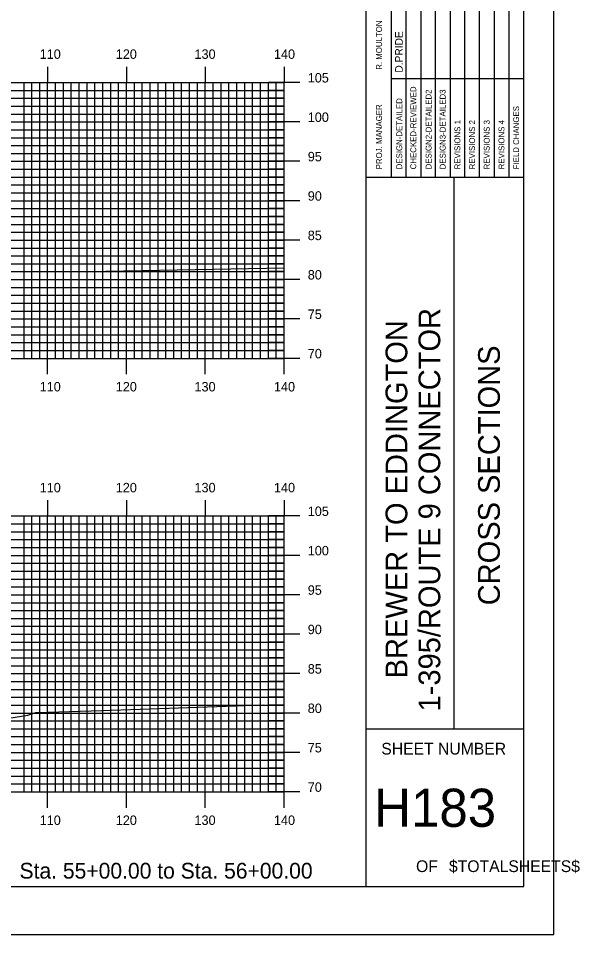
# Model space of a CAD drawing. Extents: x 1756675 to 1757019, y 442591 to 442811.
# Drawn here: x 1756947.4 to 1757018.6, y 442590.5 to 442706.8 of the extents above; entities that cross this region are included whole.
import ezdxf

# ---------------------------------------------------------------- set-up
doc = ezdxf.new("R2010")
doc.units = 0
for name, color, linetype in [('BORDER', 7, 'Continuous'), ('H_V ANNOTATION', 7, 'Continuous'), ('MAJOR', 7, 'Continuous'), ('MINOR', 7, 'Continuous'), ('PLOT BOUNDARY', 7, 'Continuous'), ('S_Roadway_Centerline', 7, 'Continuous')]:
    doc.layers.add(name, color=color, linetype=linetype)

msp = doc.modelspace()

# ---------------------------------------------------------------- linework, layer by layer
at = {"layer": 'BORDER'}
for p, q in [((1756991.48, 442596.67), (1756991.48, 442806.67)), ((1756991.48, 442686.67), (1757011.48, 442686.67)), ((1757002.66, 442616.67), (1757002.66, 442686.67)), ((1756991.48, 442616.67), (1757011.48, 442616.67))]:
    msp.add_line(p, q, dxfattribs=at)
msp.add_lwpolyline([(1756691.48, 442596.67), (1757011.48, 442596.67), (1757011.48, 442806.67), (1756691.48, 442806.67)], close=True, dxfattribs=at)
for points in [[(1756996.58, 442686.68), (1756996.58, 442721.67)], [(1756998.44, 442721.67), (1756998.44, 442686.68)], [(1757000.3, 442686.68), (1757000.3, 442721.67)], [(1757002.17, 442686.68), (1757002.17, 442721.67)], [(1757004.03, 442686.68), (1757004.03, 442721.67)], [(1757005.89, 442686.68), (1757005.89, 442721.67)], [(1757007.76, 442686.68), (1757007.76, 442721.67)], [(1757009.62, 442686.68), (1757009.62, 442721.67)], [(1756994.71, 442686.68), (1756994.71, 442720.26)], [(1756994.71, 442699.17), (1757011.48, 442699.17)]]:
    msp.add_lwpolyline(points, dxfattribs=at)
at = {"layer": 'MAJOR'}
for p, q in [((1756951.08, 442700.67), (1756951.08, 442698.67)), ((1756961.08, 442700.67), (1756961.08, 442698.67)), ((1756971.08, 442700.67), (1756971.08, 442698.67)), ((1756981.08, 442700.67), (1756981.08, 442698.67)), ((1756701.08, 442698.67), (1756981.08, 442698.67)), ((1756701.08, 442698.67), (1756981.08, 442698.67)), ((1756951.08, 442663.67), (1756951.08, 442698.67)), ((1756961.08, 442663.67), (1756961.08, 442698.67)), ((1756971.08, 442663.67), (1756971.08, 442698.67)), ((1756983.09, 442698.67), (1756979.08, 442698.67)), ((1756981.08, 442663.67), (1756981.08, 442698.67)), ((1756981.08, 442663.67), (1756981.08, 442698.67)), ((1756701.08, 442693.67), (1756981.08, 442693.67)), ((1756983.09, 442693.67), (1756979.08, 442693.67)), ((1756701.08, 442688.67), (1756981.08, 442688.67)), ((1756983.09, 442688.67), (1756979.08, 442688.67)), ((1756701.08, 442683.67), (1756981.08, 442683.67)), ((1756983.09, 442683.67), (1756979.08, 442683.67)), ((1756701.08, 442678.67), (1756981.08, 442678.67)), ((1756983.09, 442678.67), (1756979.08, 442678.67)), ((1756701.08, 442673.67), (1756981.08, 442673.67)), ((1756983.09, 442673.67), (1756979.08, 442673.67)), ((1756701.08, 442668.67), (1756981.08, 442668.67)), ((1756983.09, 442668.67), (1756979.08, 442668.67)), ((1756701.08, 442663.67), (1756981.08, 442663.67)), ((1756701.08, 442663.67), (1756981.08, 442663.67)), ((1756951.08, 442661.66), (1756951.08, 442663.67)), ((1756961.08, 442661.66), (1756961.08, 442663.67)), ((1756971.08, 442661.66), (1756971.08, 442663.67)), ((1756983.09, 442663.67), (1756979.08, 442663.67)), ((1756981.08, 442661.66), (1756981.08, 442663.67)), ((1756951.08, 442645.67), (1756951.08, 442643.67)), ((1756961.08, 442645.67), (1756961.08, 442643.67)), ((1756971.08, 442645.67), (1756971.08, 442643.67)), ((1756981.08, 442645.67), (1756981.08, 442643.67)), ((1756701.08, 442643.67), (1756981.08, 442643.67)), ((1756701.08, 442643.67), (1756981.08, 442643.67)), ((1756951.08, 442608.67), (1756951.08, 442643.67)), ((1756961.08, 442608.67), (1756961.08, 442643.67)), ((1756971.08, 442608.67), (1756971.08, 442643.67)), ((1756983.09, 442643.67), (1756979.08, 442643.67)), ((1756981.08, 442608.67), (1756981.08, 442643.67)), ((1756981.08, 442608.67), (1756981.08, 442643.67)), ((1756701.08, 442638.67), (1756981.08, 442638.67)), ((1756983.09, 442638.67), (1756979.08, 442638.67)), ((1756701.08, 442633.67), (1756981.08, 442633.67)), ((1756983.09, 442633.67), (1756979.08, 442633.67)), ((1756701.08, 442628.67), (1756981.08, 442628.67)), ((1756983.09, 442628.67), (1756979.08, 442628.67)), ((1756701.08, 442623.67), (1756981.08, 442623.67)), ((1756983.09, 442623.67), (1756979.08, 442623.67)), ((1756701.08, 442618.67), (1756981.08, 442618.67)), ((1756983.09, 442618.67), (1756979.08, 442618.67)), ((1756701.08, 442613.67), (1756981.08, 442613.67)), ((1756983.09, 442613.67), (1756979.08, 442613.67)), ((1756701.08, 442608.67), (1756981.08, 442608.67)), ((1756701.08, 442608.67), (1756981.08, 442608.67)), ((1756951.08, 442606.66), (1756951.08, 442608.67)), ((1756961.08, 442606.66), (1756961.08, 442608.67)), ((1756971.08, 442606.66), (1756971.08, 442608.67)), ((1756983.09, 442608.67), (1756979.08, 442608.67)), ((1756981.08, 442606.66), (1756981.08, 442608.67))]:
    msp.add_line(p, q, dxfattribs=at)
at = {"layer": 'MINOR'}
for p, q in [((1756948.08, 442663.67), (1756948.08, 442698.67)), ((1756949.08, 442663.67), (1756949.08, 442698.67)), ((1756950.08, 442663.67), (1756950.08, 442698.67)), ((1756952.08, 442663.67), (1756952.08, 442698.67)), ((1756953.08, 442663.67), (1756953.08, 442698.67)), ((1756954.08, 442663.67), (1756954.08, 442698.67)), ((1756955.08, 442663.67), (1756955.08, 442698.67)), ((1756956.08, 442663.67), (1756956.08, 442698.67)), ((1756957.08, 442663.67), (1756957.08, 442698.67)), ((1756958.08, 442663.67), (1756958.08, 442698.67)), ((1756959.08, 442663.67), (1756959.08, 442698.67)), ((1756960.08, 442663.67), (1756960.08, 442698.67)), ((1756962.08, 442663.67), (1756962.08, 442698.67)), ((1756963.08, 442663.67), (1756963.08, 442698.67)), ((1756964.08, 442663.67), (1756964.08, 442698.67)), ((1756965.08, 442663.67), (1756965.08, 442698.67)), ((1756966.08, 442663.67), (1756966.08, 442698.67)), ((1756967.08, 442663.67), (1756967.08, 442698.67)), ((1756968.08, 442663.67), (1756968.08, 442698.67)), ((1756969.08, 442663.67), (1756969.08, 442698.67)), ((1756970.08, 442663.67), (1756970.08, 442698.67)), ((1756972.08, 442663.67), (1756972.08, 442698.67)), ((1756973.08, 442663.67), (1756973.08, 442698.67)), ((1756974.08, 442663.67), (1756974.08, 442698.67)), ((1756975.08, 442663.67), (1756975.08, 442698.67)), ((1756976.08, 442663.67), (1756976.08, 442698.67)), ((1756977.08, 442663.67), (1756977.08, 442698.67)), ((1756978.08, 442663.67), (1756978.08, 442698.67)), ((1756979.08, 442663.67), (1756979.08, 442698.67)), ((1756980.08, 442663.67), (1756980.08, 442698.67)), ((1756701.08, 442697.67), (1756981.08, 442697.67)), ((1756981.08, 442697.67), (1756979.08, 442697.67)), ((1756701.08, 442696.67), (1756981.08, 442696.67)), ((1756981.08, 442696.67), (1756979.08, 442696.67)), ((1756701.08, 442695.67), (1756981.08, 442695.67)), ((1756981.08, 442695.67), (1756979.08, 442695.67)), ((1756701.08, 442694.67), (1756981.08, 442694.67)), ((1756981.08, 442694.67), (1756979.08, 442694.67)), ((1756701.08, 442692.67), (1756981.08, 442692.67)), ((1756701.08, 442691.67), (1756981.08, 442691.67)), ((1756981.08, 442692.67), (1756979.08, 442692.67)), ((1756981.08, 442691.67), (1756979.08, 442691.67)), ((1756701.08, 442690.67), (1756981.08, 442690.67)), ((1756981.08, 442690.67), (1756979.08, 442690.67)), ((1756701.08, 442689.67), (1756981.08, 442689.67)), ((1756981.08, 442689.67), (1756979.08, 442689.67)), ((1756701.08, 442687.67), (1756981.08, 442687.67)), ((1756981.08, 442687.67), (1756979.08, 442687.67)), ((1756701.08, 442686.67), (1756981.08, 442686.67)), ((1756981.08, 442686.67), (1756979.08, 442686.67)), ((1756701.08, 442685.67), (1756981.08, 442685.67)), ((1756701.08, 442684.67), (1756981.08, 442684.67)), ((1756981.08, 442685.67), (1756979.08, 442685.67)), ((1756981.08, 442684.67), (1756979.08, 442684.67)), ((1756701.08, 442682.67), (1756981.08, 442682.67)), ((1756981.08, 442682.67), (1756979.08, 442682.67)), ((1756701.08, 442681.67), (1756981.08, 442681.67)), ((1756981.08, 442681.67), (1756979.08, 442681.67)), ((1756701.08, 442680.67), (1756981.08, 442680.67)), ((1756981.08, 442680.67), (1756979.08, 442680.67)), ((1756701.08, 442679.67), (1756981.08, 442679.67)), ((1756981.08, 442679.67), (1756979.08, 442679.67)), ((1756701.08, 442677.67), (1756981.08, 442677.67)), ((1756701.08, 442676.67), (1756981.08, 442676.67)), ((1756981.08, 442677.67), (1756979.08, 442677.67)), ((1756981.08, 442676.67), (1756979.08, 442676.67)), ((1756701.08, 442675.67), (1756981.08, 442675.67)), ((1756981.08, 442675.67), (1756979.08, 442675.67)), ((1756701.08, 442674.67), (1756981.08, 442674.67)), ((1756981.08, 442674.67), (1756979.08, 442674.67)), ((1756701.08, 442672.67), (1756981.08, 442672.67)), ((1756981.08, 442672.67), (1756979.08, 442672.67)), ((1756701.08, 442671.67), (1756981.08, 442671.67)), ((1756981.08, 442671.67), (1756979.08, 442671.67)), ((1756701.08, 442670.67), (1756981.08, 442670.67)), ((1756701.08, 442669.67), (1756981.08, 442669.67)), ((1756981.08, 442670.67), (1756979.08, 442670.67)), ((1756981.08, 442669.67), (1756979.08, 442669.67)), ((1756701.08, 442667.67), (1756981.08, 442667.67)), ((1756981.08, 442667.67), (1756979.08, 442667.67)), ((1756701.08, 442666.67), (1756981.08, 442666.67)), ((1756981.08, 442666.67), (1756979.08, 442666.67)), ((1756701.08, 442665.67), (1756981.08, 442665.67)), ((1756981.08, 442665.67), (1756979.08, 442665.67)), ((1756701.08, 442664.67), (1756981.08, 442664.67)), ((1756981.08, 442664.67), (1756979.08, 442664.67)), ((1756948.08, 442608.67), (1756948.08, 442643.67)), ((1756949.08, 442608.67), (1756949.08, 442643.67)), ((1756950.08, 442608.67), (1756950.08, 442643.67)), ((1756952.08, 442608.67), (1756952.08, 442643.67)), ((1756953.08, 442608.67), (1756953.08, 442643.67)), ((1756954.08, 442608.67), (1756954.08, 442643.67)), ((1756955.08, 442608.67), (1756955.08, 442643.67)), ((1756956.08, 442608.67), (1756956.08, 442643.67)), ((1756957.08, 442608.67), (1756957.08, 442643.67)), ((1756958.08, 442608.67), (1756958.08, 442643.67)), ((1756959.08, 442608.67), (1756959.08, 442643.67)), ((1756960.08, 442608.67), (1756960.08, 442643.67)), ((1756962.08, 442608.67), (1756962.08, 442643.67)), ((1756963.08, 442608.67), (1756963.08, 442643.67)), ((1756964.08, 442608.67), (1756964.08, 442643.67)), ((1756965.08, 442608.67), (1756965.08, 442643.67)), ((1756966.08, 442608.67), (1756966.08, 442643.67)), ((1756967.08, 442608.67), (1756967.08, 442643.67)), ((1756968.08, 442608.67), (1756968.08, 442643.67)), ((1756969.08, 442608.67), (1756969.08, 442643.67)), ((1756970.08, 442608.67), (1756970.08, 442643.67)), ((1756972.08, 442608.67), (1756972.08, 442643.67)), ((1756973.08, 442608.67), (1756973.08, 442643.67)), ((1756974.08, 442608.67), (1756974.08, 442643.67)), ((1756975.08, 442608.67), (1756975.08, 442643.67)), ((1756976.08, 442608.67), (1756976.08, 442643.67)), ((1756977.08, 442608.67), (1756977.08, 442643.67)), ((1756978.08, 442608.67), (1756978.08, 442643.67)), ((1756979.08, 442608.67), (1756979.08, 442643.67)), ((1756980.08, 442608.67), (1756980.08, 442643.67)), ((1756701.08, 442642.67), (1756981.08, 442642.67)), ((1756701.08, 442641.67), (1756981.08, 442641.67)), ((1756981.08, 442642.67), (1756979.08, 442642.67)), ((1756981.08, 442641.67), (1756979.08, 442641.67)), ((1756701.08, 442640.67), (1756981.08, 442640.67)), ((1756981.08, 442640.67), (1756979.08, 442640.67)), ((1756701.08, 442639.67), (1756981.08, 442639.67)), ((1756981.08, 442639.67), (1756979.08, 442639.67)), ((1756701.08, 442637.67), (1756981.08, 442637.67)), ((1756981.08, 442637.67), (1756979.08, 442637.67)), ((1756701.08, 442636.67), (1756981.08, 442636.67)), ((1756981.08, 442636.67), (1756979.08, 442636.67)), ((1756701.08, 442635.67), (1756981.08, 442635.67)), ((1756701.08, 442634.67), (1756981.08, 442634.67)), ((1756981.08, 442635.67), (1756979.08, 442635.67)), ((1756981.08, 442634.67), (1756979.08, 442634.67)), ((1756701.08, 442632.67), (1756981.08, 442632.67)), ((1756981.08, 442632.67), (1756979.08, 442632.67)), ((1756701.08, 442631.67), (1756981.08, 442631.67)), ((1756981.08, 442631.67), (1756979.08, 442631.67)), ((1756701.08, 442630.67), (1756981.08, 442630.67)), ((1756981.08, 442630.67), (1756979.08, 442630.67)), ((1756701.08, 442629.67), (1756981.08, 442629.67)), ((1756981.08, 442629.67), (1756979.08, 442629.67)), ((1756701.08, 442627.67), (1756981.08, 442627.67)), ((1756701.08, 442626.67), (1756981.08, 442626.67)), ((1756981.08, 442627.67), (1756979.08, 442627.67)), ((1756981.08, 442626.67), (1756979.08, 442626.67)), ((1756701.08, 442625.67), (1756981.08, 442625.67)), ((1756981.08, 442625.67), (1756979.08, 442625.67)), ((1756701.08, 442624.67), (1756981.08, 442624.67)), ((1756981.08, 442624.67), (1756979.08, 442624.67)), ((1756701.08, 442622.67), (1756981.08, 442622.67)), ((1756981.08, 442622.67), (1756979.08, 442622.67)), ((1756701.08, 442621.67), (1756981.08, 442621.67)), ((1756981.08, 442621.67), (1756979.08, 442621.67)), ((1756701.08, 442620.67), (1756981.08, 442620.67)), ((1756701.08, 442619.67), (1756981.08, 442619.67)), ((1756981.08, 442620.67), (1756979.08, 442620.67)), ((1756981.08, 442619.67), (1756979.08, 442619.67)), ((1756701.08, 442617.67), (1756981.08, 442617.67)), ((1756981.08, 442617.67), (1756979.08, 442617.67)), ((1756701.08, 442616.67), (1756981.08, 442616.67)), ((1756981.08, 442616.67), (1756979.08, 442616.67)), ((1756701.08, 442615.67), (1756981.08, 442615.67)), ((1756981.08, 442615.67), (1756979.08, 442615.67)), ((1756701.08, 442614.67), (1756981.08, 442614.67)), ((1756981.08, 442614.67), (1756979.08, 442614.67)), ((1756701.08, 442612.67), (1756981.08, 442612.67)), ((1756981.08, 442612.67), (1756979.08, 442612.67)), ((1756701.08, 442611.67), (1756981.08, 442611.67)), ((1756981.08, 442611.67), (1756979.08, 442611.67)), ((1756701.08, 442610.67), (1756981.08, 442610.67)), ((1756981.08, 442610.67), (1756979.08, 442610.67)), ((1756701.08, 442609.67), (1756981.08, 442609.67)), ((1756981.08, 442609.67), (1756979.08, 442609.67))]:
    msp.add_line(p, q, dxfattribs=at)
at = {"layer": 'PLOT BOUNDARY'}
msp.add_lwpolyline([(1756675.3, 442590.55), (1757015.3, 442590.55), (1757015.3, 442810.55), (1756675.3, 442810.55)], close=True, dxfattribs=at)
at = {"layer": 'S_Roadway_Centerline'}
for points in [[(1756701.08, 442674.81), (1756701.68, 442674.81), (1756706.12, 442674.79), (1756709.1, 442674.81), (1756750.01, 442674.91), (1756753.92, 442674.86), (1756780.55, 442674.65), (1756793.34, 442674.46), (1756796.09, 442674.27), (1756805.61, 442673.9), (1756808.09, 442673.88), (1756821.91, 442673.54), (1756842.06, 442673.4), (1756851.64, 442673.44), (1756857.38, 442673.52), (1756881.46, 442674.48), (1756884.01, 442674.46), (1756914.99, 442674.3), (1756935.3, 442674.49), (1756942.87, 442674.67), (1756956.22, 442674.7), (1756981.08, 442675.14)], [(1756901.77, 442615.11), (1756905.48, 442615.16), (1756914.95, 442615.16), (1756921.83, 442615.2), (1756934, 442615.12), (1756936.78, 442616.05), (1756943.97, 442617.66), (1756948.57, 442618.38), (1756949.6, 442618.72), (1756949.73, 442618.73), (1756957.97, 442619.01), (1756972.56, 442619.51), (1756978.49, 442619.7), (1756980.41, 442619.67), (1756981.08, 442619.66)]]:
    msp.add_lwpolyline(points, dxfattribs=at)

# ---------------------------------------------------------------- texts
at = {"layer": 'BORDER'}
for s, height, p in [('R. MOULTON', 0.745, (1756993.49, 442700.28)), ('D.PRIDE', 0.969, (1756996.13, 442699.92)), ('CHECKED-REVIEWED', 0.7455, (1756997.84, 442687.65)), ('DESIGN2-DETAILED2', 0.7455, (1756999.78, 442687.65)), ('DESIGN3-DETAILED3', 0.7455, (1757001.57, 442687.65)), ('DESIGN-DETAILED', 0.7455, (1756996.06, 442687.65)), ('PROJ. MANAGER', 0.7455, (1756993.49, 442687.65)), ('FIELD CHANGES', 0.7455, (1757010.89, 442687.65)), ('REVISIONS 1', 0.7455, (1757003.44, 442687.65)), ('REVISIONS 2', 0.7455, (1757005.3, 442687.65)), ('REVISIONS 3', 0.7455, (1757007.16, 442687.65)), ('REVISIONS 4', 0.7455, (1757009.03, 442687.65)), ('1-395/ROUTE 9 CONNECTOR', 2.7557, (1757000.89, 442618.87)), ('BREWER TO EDDINGTON', 2.7557, (1756996.71, 442623.07)), ('CROSS SECTIONS', 2.7557, (1757008.45, 442632.34))]:
    msp.add_text(s, height=height, rotation=90, dxfattribs=at).set_placement(p)
for s, height, p in [('SHEET NUMBER', 1.4905, (1756993.41, 442613.4)), ('H183', 4.839, (1756992.51, 442604.23)), ('OF', 1.491, (1756997.82, 442598.49)), ('$TOTALSHEETS$', 1.4905, (1757002, 442598.49))]:
    msp.add_text(s, height=height, dxfattribs=at).set_placement(p)
at = {"layer": 'H_V ANNOTATION'}
for s, height, p in [('110', 1.2, (1756950.07, 442701.67)), ('120', 1.2, (1756959.72, 442701.67)), ('130', 1.2, (1756969.71, 442701.67)), ('140', 1.2, (1756979.79, 442701.67)), ('105', 1.2, (1756984.08, 442698.67)), ('100', 1.2, (1756984.08, 442693.67)), ('95', 1.2, (1756984.08, 442688.67)), ('90', 1.2, (1756984.08, 442683.67)), ('85', 1.2, (1756984.08, 442678.67)), ('80', 1.2, (1756984.08, 442673.67)), ('75', 1.2, (1756984.08, 442668.67)), ('70', 1.2, (1756984.08, 442663.67)), ('110', 1.2, (1756950.07, 442659.47)), ('120', 1.2, (1756959.72, 442659.47)), ('130', 1.2, (1756969.71, 442659.47)), ('140', 1.2, (1756979.79, 442659.47)), ('110', 1.2, (1756950.07, 442646.67)), ('120', 1.2, (1756959.72, 442646.67)), ('130', 1.2, (1756969.71, 442646.67)), ('140', 1.2, (1756979.79, 442646.67)), ('105', 1.2, (1756984.08, 442643.67)), ('100', 1.2, (1756984.08, 442638.67)), ('95', 1.2, (1756984.08, 442633.67)), ('90', 1.2, (1756984.08, 442628.67)), ('85', 1.2, (1756984.08, 442623.67)), ('80', 1.2, (1756984.08, 442618.67)), ('75', 1.2, (1756984.08, 442613.67)), ('70', 1.2, (1756984.08, 442608.67)), ('110', 1.2, (1756950.07, 442604.47)), ('120', 1.2, (1756959.72, 442604.47)), ('130', 1.2, (1756969.71, 442604.47)), ('140', 1.2, (1756979.79, 442604.47)), ('Sta. 55+00.00 to Sta. 56+00.00', 2.0004, (1756947.51, 442597.66))]:
    msp.add_text(s, height=height, dxfattribs=at).set_placement(p)

doc.saveas('drawing.dxf')
